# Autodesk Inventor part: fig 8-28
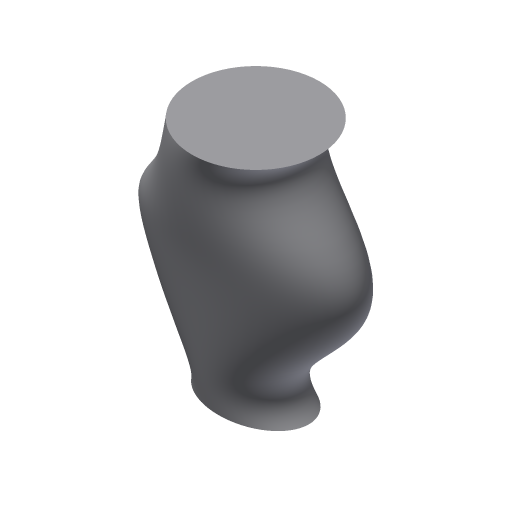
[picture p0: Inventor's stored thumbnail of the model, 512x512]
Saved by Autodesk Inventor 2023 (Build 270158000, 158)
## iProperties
Part Number: fig 8-28
Document SubType Name: Modeling
Created: 2002-12
Designer: deepak
Density: 1 g/cm^3
Material: Generic
Appearance: Default
Control State: 0
Master: False
Checked Out: False
Shininess: 64.0
Length Units: 11269
Angle Units: 11279
Time Units: 11290
Mass Units: 11283
Length Display Precision: 3
Angle Display Precision: 2
Compacted: True
Density: 0.0
Volumn: 0.0
Area: 0.0
PropertySet Name: Model Information
Author: deepak
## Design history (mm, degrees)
sketch "Sketch1"
  geometry: 2 further points; 1 other entity
  constraints: 1 coincident, 3 other
workplane "Work Plane1"
workplane "Work Plane2"
sketch "Sketch3"
  geometry: C1 r 60 at (0, 0); 1 further point
  constraints: 1 centre point, 1 coincident, 1 other
sketch "Sketch4"
  geometry: 8 further points
  constraints: 8 other
sketch "Sketch5"
  geometry: 6 further points
  constraints: 6 other
sketch "Sketch6"
  geometry: 6 further points
  constraints: 6 other
  dimensions: "d20" = 35 distance of point (0, 0) point (-35, 0); "d21" = 0 vertical distance of point (0, 0) point (-35, 0); "d22" = 225 vertical distance of point (0, 0) point (-60, 225); "d23" = 60 horizontal distance of point (0, 0) point (-60, 225); "d24" = 100 horizontal distance of point (0, 0) point (-100, 125); "d25" = 125 vertical distance of point (0, 0) point (-100, 125)
loft "Loft5" dims "d54" = 0, "d55" = 90 deg, "d56" = 0, "d57" = 90 deg, "d58" = 0, "d59" = 90 deg, "d60" = 0, "d61" = 90 deg
body "Solid2"
other parameters: "d5" = 125
